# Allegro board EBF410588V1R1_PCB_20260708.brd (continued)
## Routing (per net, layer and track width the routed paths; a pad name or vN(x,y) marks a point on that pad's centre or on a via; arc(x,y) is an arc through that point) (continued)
MIPI_DPHY_CSI1_RX_D0N: length 73.6
  TOP w0.084: v1(13.26,46.28) 13.13,46.16 arc(13,46.07) 12.85,46.04 11.98,46.04 arc(11.67,45.98) 11.41,45.81 11.41,45.8 arc(11.29,45.52) 11.41,45.23 11.51,45.13 arc(11.57,44.98) 11.51,44.83 11.46,44.79 arc(11.35,44.74) 11.23,44.79 11.16,44.86 arc(10.81,45) 10.46,44.86 10.32,44.71 arc(10.22,44.48) 10.32,44.24 10.37,44.19 arc(10.37,43.89) 10.08,43.89 arc(9.79,44.01) 9.5,43.89 9.41,43.8 arc(9.2,43.49) 9.12,43.11 9.12,42.75 arc(9.09,42.59) 9,42.45 8.75,42.2 arc(8.48,41.8) 8.39,41.32 8.39,40.33 arc(8.36,40.18) 8.27,40.04 8.07,39.84 arc(7.85,39.52) 7.78,39.15 7.78,37.03 arc(7.74,36.94) 7.64,36.9 7.6,36.9 arc(7.51,36.92) 7.44,36.97 7.42,36.98 arc(7.35,37.03) 7.26,37.05 J15.12 ; v1(62.92,51.79) 62.92,51.63 arc(62.9,51.5) 62.83,51.4 62.61,51.18 arc(62.5,51.01) 62.46,50.81 62.46,50.79 arc(62.5,50.59) 62.61,50.42 62.8,50.23 arc(62.82,50.2) 62.82,50.17 62.82,49.65 arc(62.81,49.59) 62.78,49.54 62.77,49.53 arc(62.73,49.48) 62.72,49.42 CN2.54
  BOTTOM w0.084: v1(62.92,51.79) 62.92,51.61 arc(62.89,51.45) 62.81,51.33 62.54,51.06 arc(62.46,50.94) 62.43,50.79 62.43,50.62 62.23,50.42 arc(62.03,50.28) 61.79,50.24 52.05,50.24 arc(51.41,50.11) 50.86,49.74 45.51,44.4 arc(45.03,44.08) 44.47,43.96 42.76,43.96 arc(42.2,44.08) 41.72,44.4 41.65,44.46 arc(41.11,44.83) 40.47,44.95 36.04,44.95 arc(35.4,44.83) 34.85,44.46 34.1,43.71 arc(33.62,43.39) 33.06,43.28 21.93,43.28 arc(21.36,43.39) 20.88,43.71 18.75,45.84 arc(18.53,45.99) 18.27,46.04 13.67,46.04 arc(13.52,46.07) 13.39,46.16 v1(13.26,46.28)
MIPI_DPHY_CSI1_RX_D0P: length 73.7
  TOP w0.084: v1(13.26,45.4) 13.3,45.44 arc(13.33,45.48) 13.34,45.52 13.34,45.58 arc(13.32,45.66) 13.27,45.73 13.24,45.76 arc(13.15,45.82) 13.05,45.84 11.98,45.84 arc(11.75,45.8) 11.55,45.67 11.55,45.66 arc(11.49,45.52) 11.55,45.37 11.65,45.27 arc(11.77,44.98) 11.65,44.69 11.6,44.65 arc(11.35,44.54) 11.09,44.65 11.02,44.72 arc(10.81,44.8) 10.6,44.72 10.46,44.57 arc(10.42,44.48) 10.46,44.38 10.51,44.33 arc(10.51,43.75) 9.94,43.75 arc(9.79,43.82) 9.64,43.75 9.55,43.66 arc(9.38,43.41) 9.32,43.11 9.32,42.75 arc(9.27,42.51) 9.14,42.31 8.89,42.06 arc(8.66,41.72) 8.59,41.32 8.59,40.33 arc(8.54,40.1) 8.41,39.9 8.21,39.7 arc(8.04,39.45) 7.98,39.15 7.98,37.03 arc(7.88,36.8) 7.64,36.7 7.6,36.7 arc(7.51,36.68) 7.43,36.63 7.42,36.62 arc(7.35,36.57) 7.26,36.55 J15.11 ; v1(62.92,50.79) 62.84,50.7 arc(62.8,50.61) 62.84,50.52 62.94,50.42 arc(63,50.33) 63.02,50.22 63.02,49.65 arc(63.03,49.59) 63.07,49.54 63.08,49.53 arc(63.11,49.48) 63.12,49.42 CN2.56
  BOTTOM w0.084: v1(62.92,50.79) 62.76,50.79 62.63,50.65 62.63,50.54 62.37,50.28 arc(62.1,50.1) 61.79,50.04 52.05,50.04 arc(51.48,49.93) 51,49.6 45.65,44.26 arc(45.11,43.89) 44.47,43.77 42.76,43.77 arc(42.12,43.89) 41.58,44.26 41.51,44.32 arc(41.03,44.64) 40.47,44.75 36.04,44.75 arc(35.47,44.64) 34.99,44.32 34.24,43.57 arc(33.7,43.21) 33.06,43.08 21.93,43.08 arc(21.29,43.21) 20.74,43.57 18.61,45.7 arc(18.45,45.81) 18.27,45.84 18.12,45.84 arc(18.07,45.82) 18.05,45.77 arc(18.03,45.72) 17.98,45.69 17.79,45.69 arc(17.74,45.72) 17.72,45.77 arc(17.69,45.82) 17.64,45.84 17.45,45.84 arc(17.4,45.82) 17.38,45.77 arc(17.36,45.72) 17.31,45.69 17.12,45.69 arc(17.07,45.72) 17.04,45.77 arc(17.02,45.82) 16.97,45.84 16.78,45.84 arc(16.73,45.82) 16.71,45.77 arc(16.69,45.72) 16.64,45.69 16.45,45.69 arc(16.4,45.72) 16.37,45.77 arc(16.35,45.82) 16.3,45.84 16.11,45.84 arc(16.06,45.82) 16.04,45.77 arc(16.02,45.72) 15.96,45.69 15.78,45.69 arc(15.73,45.72) 15.7,45.77 arc(15.68,45.82) 15.63,45.84 15.44,45.84 arc(15.39,45.82) 15.37,45.77 arc(15.35,45.72) 15.29,45.69 15.11,45.69 arc(15.05,45.72) 15.03,45.77 arc(15.01,45.82) 14.96,45.84 14.77,45.84 arc(14.72,45.82) 14.7,45.77 arc(14.68,45.72) 14.62,45.69 14.44,45.69 arc(14.38,45.72) 14.36,45.77 arc(14.34,45.82) 14.29,45.84 14.1,45.84 arc(14.05,45.82) 14.03,45.77 arc(14.01,45.72) 13.95,45.69 13.77,45.69 arc(13.71,45.72) 13.69,45.77 arc(13.67,45.82) 13.62,45.84 13.36,45.84 arc(13.29,45.81) 13.26,45.75 v1(13.26,45.4)
MIPI_DPHY_CSI1_RX_D1N: length 73.7
  TOP w0.084: v1(63.92,51.79) 63.92,51.6 arc(63.89,51.44) 63.8,51.3 63.6,51.1 arc(63.49,50.94) 63.45,50.74 63.45,50.64 arc(63.47,50.53) 63.53,50.44 63.54,50.43 arc(63.6,50.34) 63.62,50.23 63.62,49.65 arc(63.61,49.59) 63.58,49.54 63.57,49.53 arc(63.53,49.48) 63.52,49.42 CN2.58 ; J15.8 7.26,35.05 arc(7.35,35.03) 7.42,34.98 7.43,34.97 arc(7.51,34.92) 7.6,34.9 7.75,34.9 arc(7.96,34.94) 8.13,35.06 8.74,35.66 arc(9.06,36.14) 9.17,36.71 9.17,38.42 arc(9.21,38.62) 9.32,38.78 9.65,39.11 arc(9.91,39.51) 10.01,39.98 10.01,41.27 arc(10.07,41.6) 10.26,41.89 11.37,42.99 arc(12,43.25) 12.64,42.99 arc(12.83,42.86) 13.05,42.82 13.47,42.82 arc(13.74,42.87) 13.97,43.02 13.98,43.04 arc(14.11,43.24) 14.16,43.47 14.16,43.9 arc(14.19,44.04) 14.27,44.16 14.46,44.36 arc(14.58,44.44) 14.72,44.47 14.95,44.47 arc(15.07,44.49) 15.17,44.55 15.23,44.62 arc(15.26,44.66) 15.27,44.7 v1(15.27,44.76)
  BOTTOM w0.084: v1(15.27,44.76) 15.39,44.63 arc(15.52,44.55) 15.68,44.52 17.81,44.52 arc(17.93,44.49) 18.04,44.42 19.79,42.66 arc(20.04,42.5) 20.33,42.44 33.58,42.44 arc(34.15,42.56) 34.63,42.88 35.25,43.5 arc(35.8,43.87) 36.44,43.99 40.07,43.99 arc(40.71,43.87) 41.25,43.5 41.32,43.44 arc(41.8,43.12) 42.36,43 45.01,43 arc(45.57,43.12) 46.05,43.44 51.5,48.89 arc(52.05,49.25) 52.69,49.38 62.3,49.38 arc(62.38,49.39) 62.44,49.44 63.42,50.42 63.42,50.69 arc(63.47,50.93) 63.6,51.13 63.81,51.34 arc(63.89,51.46) 63.92,51.61 v1(63.92,51.79)
MIPI_DPHY_CSI1_RX_D1P: length 73.8
  TOP w0.084: v1(63.92,50.79) 63.87,50.73 arc(63.83,50.68) 63.82,50.62 63.82,49.65 arc(63.83,49.59) 63.87,49.54 63.88,49.53 arc(63.91,49.48) 63.92,49.42 CN2.60 ; v1(15.27,43.87) 15.27,44.01 arc(15.24,44.11) 15.19,44.2 arc(15.11,44.25) 15.02,44.27 14.72,44.27 arc(14.66,44.26) 14.6,44.22 14.41,44.02 arc(14.37,43.97) 14.36,43.9 14.36,43.47 arc(14.3,43.16) 14.12,42.9 14.11,42.88 arc(13.81,42.69) 13.47,42.62 13.05,42.62 arc(12.75,42.68) 12.5,42.85 arc(12,43.05) 11.51,42.85 10.4,41.75 arc(10.26,41.53) 10.21,41.27 10.21,39.98 arc(10.1,39.43) 9.79,38.97 9.46,38.64 arc(9.39,38.54) 9.37,38.42 9.37,36.71 arc(9.24,36.06) 8.88,35.52 8.27,34.92 arc(8.03,34.76) 7.75,34.7 7.6,34.7 arc(7.51,34.68) 7.44,34.63 7.42,34.62 arc(7.35,34.57) 7.26,34.55 J15.7
  BOTTOM w0.084: v1(63.92,50.79) 63.75,50.79 63.62,50.65 63.62,50.33 63.47,50.18 arc(63.45,50.13) 63.47,50.08 arc(63.49,50.03) 63.47,49.98 63.33,49.84 arc(63.28,49.82) 63.23,49.84 63.23,49.85 arc(63.18,49.87) 63.13,49.85 62.99,49.71 arc(62.97,49.66) 62.99,49.61 arc(63.01,49.56) 62.99,49.51 62.86,49.37 arc(62.81,49.35) 62.76,49.37 arc(62.71,49.39) 62.66,49.37 62.58,49.3 arc(62.45,49.21) 62.3,49.18 52.69,49.18 arc(52.12,49.07) 51.64,48.75 46.19,43.3 arc(45.65,42.93) 45.01,42.81 42.36,42.81 arc(41.72,42.93) 41.18,43.3 41.11,43.36 arc(40.63,43.68) 40.07,43.79 36.44,43.79 arc(35.87,43.68) 35.39,43.36 34.77,42.74 arc(34.22,42.37) 33.58,42.25 20.3,42.25 arc(19.96,42.31) 19.68,42.5 19.31,42.87 arc(19.25,42.89) 19.2,42.87 arc(19.14,42.84) 19.08,42.87 18.96,42.99 arc(18.94,43.05) 18.96,43.11 arc(18.98,43.16) 18.96,43.22 18.84,43.34 arc(18.78,43.37) 18.72,43.34 arc(18.66,43.32) 18.61,43.34 18.48,43.47 arc(18.46,43.52) 18.48,43.58 arc(18.51,43.64) 18.48,43.69 18.36,43.82 arc(18.3,43.84) 18.25,43.82 18.25,43.82 arc(18.19,43.79) 18.13,43.82 18.01,43.94 arc(17.99,44) 18.01,44.05 arc(18.03,44.11) 18.01,44.17 17.9,44.28 arc(17.86,44.31) 17.81,44.32 17.45,44.32 arc(17.39,44.3) 17.37,44.24 arc(17.35,44.19) 17.3,44.17 17.11,44.17 arc(17.06,44.19) 17.04,44.24 arc(17.02,44.3) 16.96,44.32 16.78,44.32 arc(16.72,44.3) 16.7,44.24 arc(16.68,44.19) 16.63,44.17 16.44,44.17 arc(16.39,44.19) 16.37,44.24 arc(16.35,44.3) 16.29,44.32 16.11,44.32 arc(16.05,44.3) 16.03,44.24 arc(16.01,44.19) 15.96,44.17 15.77,44.17 arc(15.72,44.19) 15.7,44.24 arc(15.67,44.3) 15.62,44.32 15.42,44.32 arc(15.34,44.3) 15.28,44.26 15.27,44.25 arc(15.19,44.06) v1(15.27,43.87)
MIPI_DPHY_CSI2_RX_CLKN: length 93.6
  TOP w0.084: CN2.76 67.12,49.42 arc(67.13,49.48) 67.17,49.53 67.18,49.54 arc(67.21,49.59) 67.22,49.65 67.22,49.93 arc(67.25,50.05) 67.31,50.14 67.35,50.18 arc(67.43,50.3) 67.46,50.45 67.46,50.81 arc(67.49,50.96) 67.58,51.1 67.81,51.32 arc(67.89,51.45) 67.92,51.6 v1(67.92,51.79)
  ART03 w0.076: v1(3.74,18.78) 3.63,18.88 arc(3.53,18.95) 3.41,18.98 3.19,18.98 arc(2.82,19.13) 2.67,19.5 2.67,21.73 arc(2.69,21.86) 2.77,21.97 2.83,22.03 arc(2.86,22.08) 2.87,22.13 2.87,24.42 arc(2.99,25) 3.32,25.5 5.22,27.4 6.52,28.7 arc(6.81,29.13) 6.91,29.64 6.91,30.4 arc(7.12,31.49) 7.74,32.41 8.08,32.75 arc(8.28,33.06) 8.36,33.43 8.36,34.08 arc(8.5,34.82) 8.93,35.45 8.93,35.46 arc(9.55,35.87) 10.28,36.02 11.66,36.02 arc(11.82,36.05) 11.96,36.14 12.04,36.22 v1(12.04,36.24)
  BOTTOM w0.084: v1(3.74,18.78) 3.86,18.9 arc(3.98,18.98) 4.12,19 4.46,19 arc(4.78,19.07) 5.05,19.25 5.23,19.42 arc(5.31,19.48) 5.41,19.5 5.51,19.5 arc(5.61,19.48) 5.68,19.43 5.69,19.42 arc(5.77,19.37) 5.86,19.35 J16.10 ; v1(67.92,51.79) 67.92,51.62 arc(67.89,51.48) 67.81,51.36 67.59,51.13 arc(67.45,50.92) 67.4,50.67 67.4,48.76 arc(67.39,48.71) 67.36,48.67 64.64,45.95 arc(64.16,45.62) 63.59,45.51 54.84,45.51 arc(54.2,45.38) 53.66,45.02 47.63,38.99 arc(47.15,38.67) 46.58,38.56 41.35,38.56 arc(40.93,38.64) 40.57,38.88 40.51,38.94 arc(40.1,39.22) 39.61,39.31 21.29,39.31 arc(20.65,39.19) 20.1,38.82 17.66,36.38 arc(17.18,36.06) 16.62,35.95 12.53,35.95 arc(12.35,35.99) 12.19,36.09 v1(12.04,36.24)
MIPI_DPHY_CSI2_RX_CLKP: length 93.7
  TOP w0.084: v1(67.92,50.79) 67.83,50.79 arc(67.71,50.74) 67.67,50.62 67.67,50.38 arc(67.64,50.23) 67.55,50.1 67.45,50 arc(67.43,49.97) 67.42,49.93 67.42,49.65 arc(67.43,49.59) 67.47,49.54 67.48,49.53 arc(67.51,49.48) 67.52,49.42 CN2.78
  ART03 w0.076: v1(3.74,19.58) 3.74,19.48 arc(3.72,19.39) 3.68,19.32 3.63,19.28 arc(3.52,19.2) 3.39,19.18 3.19,19.18 arc(2.96,19.27) 2.87,19.5 2.87,21.73 arc(2.88,21.78) 2.91,21.82 2.98,21.89 arc(3.05,22) 3.07,22.13 3.07,24.42 arc(3.17,24.93) 3.46,25.36 5.36,27.25 6.67,28.56 arc(7,29.05) 7.11,29.64 7.11,30.4 arc(7.31,31.41) 7.88,32.27 8.22,32.6 arc(8.47,32.98) 8.56,33.43 8.56,34.08 arc(8.69,34.74) 9.07,35.31 9.07,35.31 arc(9.63,35.68) 10.28,35.81 11.79,35.81 arc(11.9,35.79) 12,35.73 12.04,35.69 arc(12.11,35.52) v1(12.04,35.36)
  BOTTOM w0.084: J16.9 5.86,19.85 arc(5.77,19.83) 5.69,19.78 5.68,19.77 arc(5.61,19.72) 5.51,19.7 5.41,19.7 arc(5.24,19.66) 5.09,19.56 4.91,19.39 arc(4.7,19.25) 4.46,19.2 4.03,19.2 arc(3.92,19.22) 3.83,19.28 3.81,19.31 arc(3.76,19.38) 3.74,19.47 v1(3.74,19.58) ; v1(12.04,35.36) 12.02,35.38 arc(11.96,35.51) 12.02,35.64 arc(12.14,35.72) 12.29,35.75 12.62,35.75 arc(12.67,35.73) 12.69,35.68 arc(12.71,35.63) 12.76,35.61 12.95,35.61 arc(13,35.63) 13.02,35.68 arc(13.04,35.73) 13.09,35.75 13.29,35.75 arc(13.34,35.73) 13.36,35.68 arc(13.38,35.63) 13.43,35.61 13.62,35.61 arc(13.67,35.63) 13.69,35.68 arc(13.71,35.73) 13.76,35.75 16.62,35.75 arc(17.26,35.88) 17.8,36.24 20.24,38.68 arc(20.72,39) 21.29,39.12 39.61,39.12 arc(40.02,39.03) 40.37,38.8 40.43,38.74 arc(40.85,38.46) 41.35,38.36 46.58,38.36 arc(47.22,38.49) 47.77,38.85 53.8,44.88 arc(54.28,45.2) 54.84,45.31 63.59,45.31 arc(64.24,45.44) 64.78,45.8 66.14,47.16 arc(66.2,47.19) 66.26,47.16 arc(66.33,47.13) 66.39,47.16 66.5,47.27 arc(66.53,47.33) 66.5,47.4 arc(66.47,47.46) 66.5,47.52 66.61,47.64 arc(66.67,47.66) 66.74,47.64 arc(66.8,47.61) 66.86,47.64 66.97,47.75 arc(67,47.81) 66.97,47.87 arc(66.95,47.94) 66.97,48 67.08,48.11 arc(67.15,48.14) 67.21,48.11 arc(67.27,48.08) 67.34,48.11 67.45,48.22 arc(67.47,48.28) 67.45,48.35 arc(67.42,48.41) 67.45,48.47 67.6,48.62 67.6,49.21 arc(67.62,49.27) 67.68,49.29 arc(67.74,49.32) 67.77,49.38 67.77,49.54 arc(67.74,49.6) 67.68,49.63 arc(67.62,49.65) 67.6,49.71 67.6,49.88 arc(67.62,49.94) 67.68,49.96 arc(67.74,49.99) 67.77,50.05 67.77,50.21 arc(67.74,50.27) 67.68,50.3 arc(67.62,50.32) 67.6,50.38 67.6,50.63 67.75,50.79 v1(67.92,50.79)
MIPI_DPHY_CSI2_RX_D0N: length 95.8
  TOP w0.084: v1(65.92,51.79) 65.92,51.61 arc(65.89,51.46) 65.81,51.33 65.59,51.12 arc(65.49,50.96) 65.46,50.78 65.46,50.68 arc(65.48,50.58) 65.53,50.49 65.55,50.48 arc(65.6,50.4) 65.62,50.29 65.62,49.65 arc(65.61,49.59) 65.58,49.54 65.57,49.53 arc(65.53,49.48) 65.52,49.42 CN2.68
  ART03 w0.076: v1(10.11,37.61) 10,37.5 arc(9.88,37.42) 9.75,37.4 9.49,37.4 arc(9.12,37.32) 8.81,37.12 8.49,36.79 arc(7.94,35.97) 7.75,35 7.75,34.52 arc(7.69,34.24) 7.53,34 6.61,33.08 arc(6.24,32.52) 6.1,31.86 arc(6.1,31.84) 6.1,31.83 6.1,29.66 arc(6.07,29.53) 6,29.43 1.84,25.27 arc(1.51,24.78) 1.4,24.19 1.4,19.56 arc(1.44,19.32) 1.58,19.12 1.6,19.1 arc(1.67,18.94) 1.6,18.78 1.5,18.67 arc(1.42,18.56) 1.4,18.43 1.4,17.78 arc(1.52,17.48) 1.83,17.35 1.91,17.35 arc(2.02,17.33) 2.11,17.27 v1(2.29,17.09)
  BOTTOM w0.084: v1(65.92,51.79) 65.96,51.74 arc(66.02,51.61) 65.96,51.48 65.62,51.14 arc(65.5,50.96) 65.46,50.75 65.46,50.31 65.58,50.19 65.58,49.66 arc(65.57,49.61) 65.54,49.57 64,48.02 arc(63.81,47.89) 63.58,47.85 54.41,47.85 arc(53.77,47.72) 53.22,47.36 47.37,41.5 arc(46.89,41.18) 46.32,41.07 41.12,41.07 arc(40.95,41.03) 40.81,40.94 40.75,40.88 arc(40.68,40.83) 40.59,40.81 19.76,40.81 arc(19.12,40.69) 18.58,40.32 16.75,38.49 arc(16.23,38.14) 15.62,38.02 11.65,38.02 arc(11.49,37.99) 11.36,37.91 10.94,37.48 arc(10.78,37.38) 10.6,37.34 10.56,37.34 arc(10.39,37.38) 10.25,37.47 v1(10.11,37.61) ; v1(2.29,17.09) 2.41,17.21 arc(2.53,17.29) 2.68,17.32 3.63,17.32 arc(4.01,17.4) 4.33,17.61 5.09,18.38 arc(5.23,18.47) 5.39,18.5 5.51,18.5 arc(5.61,18.48) 5.68,18.43 5.69,18.42 arc(5.77,18.37) 5.86,18.35 J16.12
MIPI_DPHY_CSI2_RX_D0P: length 95.9
  TOP w0.084: v1(65.92,50.79) 65.87,50.73 arc(65.83,50.68) 65.82,50.62 65.82,49.65 arc(65.83,49.59) 65.87,49.54 65.88,49.53 arc(65.91,49.48) 65.92,49.42 CN2.70
  ART03 w0.076: v1(10.11,36.72) 10.11,36.92 arc(10.03,37.11) 9.84,37.19 9.49,37.19 arc(9.2,37.13) 8.96,36.97 8.63,36.65 arc(8.13,35.89) 7.95,35 7.95,34.52 arc(7.88,34.16) 7.67,33.85 6.76,32.94 arc(6.42,32.44) 6.3,31.86 6.3,29.66 arc(6.26,29.46) 6.14,29.28 1.99,25.13 arc(1.7,24.7) 1.6,24.19 1.6,19.56 arc(1.63,19.4) 1.72,19.27 1.74,19.24 arc(1.87,18.94) 1.74,18.63 1.64,18.53 arc(1.61,18.48) 1.6,18.43 1.6,17.78 arc(1.67,17.62) 1.83,17.55 2.07,17.55 arc(2.22,17.61) 2.29,17.77 v1(2.29,17.98)
  BOTTOM w0.084: v1(65.92,50.79) 65.8,50.79 65.66,50.65 65.66,50.4 65.78,50.27 65.78,49.52 65.63,49.38 arc(65.6,49.31) 65.63,49.25 arc(65.66,49.18) 65.63,49.12 65.52,49.01 arc(65.46,48.98) 65.39,49.01 arc(65.33,49.04) 65.27,49.01 65.16,48.9 arc(65.13,48.84) 65.16,48.77 arc(65.18,48.71) 65.16,48.65 65.05,48.54 arc(64.98,48.51) 64.92,48.54 arc(64.86,48.56) 64.79,48.54 64.68,48.43 arc(64.66,48.36) 64.68,48.3 arc(64.71,48.24) 64.68,48.17 64.57,48.06 arc(64.51,48.04) 64.45,48.06 arc(64.38,48.09) 64.32,48.06 64.14,47.88 arc(63.88,47.71) 63.58,47.65 54.41,47.65 arc(53.84,47.54) 53.36,47.22 47.51,41.36 arc(46.96,41) 46.32,40.87 41.12,40.87 arc(41.03,40.85) 40.95,40.8 40.89,40.74 arc(40.75,40.65) 40.59,40.61 19.76,40.61 arc(19.2,40.5) 18.72,40.18 16.85,38.32 arc(16.31,37.95) 15.67,37.83 14.95,37.83 arc(14.89,37.8) 14.87,37.75 arc(14.85,37.69) 14.79,37.67 14.61,37.67 arc(14.56,37.69) 14.53,37.75 arc(14.51,37.8) 14.46,37.83 14.28,37.83 arc(14.22,37.8) 14.2,37.75 arc(14.18,37.69) 14.12,37.67 13.94,37.67 arc(13.89,37.69) 13.86,37.75 arc(13.84,37.8) 13.79,37.83 13.61,37.83 arc(13.55,37.8) 13.53,37.75 arc(13.51,37.69) 13.45,37.67 13.27,37.67 arc(13.22,37.69) 13.19,37.75 arc(13.17,37.8) 13.12,37.83 12.94,37.83 arc(12.88,37.8) 12.86,37.75 arc(12.84,37.69) 12.78,37.67 12.6,37.67 arc(12.55,37.69) 12.52,37.75 arc(12.5,37.8) 12.44,37.83 12.27,37.83 arc(12.21,37.8) 12.19,37.75 arc(12.16,37.69) 12.11,37.67 11.93,37.67 arc(11.88,37.69) 11.85,37.75 arc(11.83,37.8) 11.77,37.83 11.65,37.83 arc(11.57,37.81) 11.5,37.77 11.08,37.34 arc(10.86,37.2) 10.6,37.14 10.22,37.14 arc(10.14,37.11) 10.11,37.03 v1(10.11,36.72) ; J16.11 5.86,18.85 arc(5.77,18.83) 5.69,18.78 5.68,18.77 arc(5.61,18.72) 5.51,18.7 5.39,18.7 arc(5.15,18.65) 4.95,18.52 4.19,17.75 arc(3.93,17.58) 3.63,17.52 2.55,17.52 arc(2.45,17.54) 2.37,17.59 2.36,17.61 arc(2.3,17.69) 2.29,17.78 v1(2.29,17.98)
MIPI_DPHY_CSI2_RX_D1N: length 96.1
  TOP w0.084: v1(66.92,51.79) 66.92,51.61 arc(66.89,51.47) 66.81,51.34 66.59,51.12 arc(66.47,50.94) 66.42,50.72 66.42,49.65 arc(66.41,49.59) 66.38,49.54 66.37,49.53 arc(66.33,49.48) 66.32,49.42 CN2.72
  ART03 w0.076: v1(10.11,35.1) 9.98,34.97 arc(9.86,34.88) 9.7,34.85 9.49,34.85 arc(9.31,34.82) 9.15,34.71 arc(9.08,34.6) 9.05,34.46 9.05,33.42 arc(8.88,32.56) 8.4,31.84 7.96,31.41 arc(7.8,31.17) 7.75,30.89 7.75,28.36 arc(7.69,28.22) 7.56,28.17 7.28,28.17 arc(7,28.05) 6.88,27.77 6.88,27.76 arc(7,27.49) 7.27,27.38 7.56,27.38 arc(7.69,27.32) 7.75,27.19 7.75,26.98 arc(7.69,26.85) 7.56,26.79 6.26,26.79 arc(5.87,26.4) 6.26,26.01 7.45,26.01 arc(7.66,25.92) 7.75,25.71 7.75,25.61 arc(7.69,25.46) 7.54,25.4 4.5,25.4 arc(4.1,25.24) 3.94,24.84 3.94,22.03 arc(3.92,21.96) 3.89,21.9 3.82,21.84 arc(3.74,21.71) 3.71,21.56 3.71,20.83 arc(3.83,20.54) 4.12,20.42 arc(4.27,20.39) 4.4,20.31 v1(4.52,20.18)
  BOTTOM w0.084: J16.8 5.86,20.35 arc(5.77,20.37) 5.69,20.42 5.68,20.43 arc(5.61,20.48) 5.51,20.5 5.06,20.5 arc(4.86,20.46) 4.69,20.35 v1(4.52,20.18) ; v1(66.92,51.79) 66.92,51.61 arc(66.89,51.45) 66.81,51.33 66.59,51.11 arc(66.46,50.91) 66.41,50.66 66.41,49.04 arc(66.4,48.99) 66.37,48.94 64.35,46.93 arc(63.87,46.61) 63.3,46.49 54.45,46.49 arc(53.81,46.37) 53.27,46 47.21,39.95 arc(46.73,39.63) 46.17,39.52 41.57,39.52 arc(41.26,39.58) 40.99,39.76 40.92,39.82 arc(40.6,40.04) 40.21,40.12 20.52,40.12 arc(19.88,39.99) 19.33,39.63 17.19,37.49 arc(16.71,37.17) 16.15,37.05 11.92,37.05 arc(11.7,37.01) 11.51,36.89 11.5,36.87 arc(11.37,36.69) 11.33,36.47 11.33,35.37 arc(11.18,35.02) 10.84,34.88 10.47,34.88 arc(10.34,34.9) 10.22,34.98 v1(10.11,35.1)
MIPI_DPHY_CSI2_RX_D1P: length 96
  TOP w0.084: CN2.74 66.72,49.42 arc(66.71,49.48) 66.68,49.53 66.67,49.54 arc(66.63,49.59) 66.62,49.65 66.62,50.7 arc(66.65,50.76) 66.71,50.79 v1(66.92,50.79)
  ART03 w0.076: v1(10.11,34.21) 10.11,34.38 arc(10.03,34.57) 9.84,34.65 9.49,34.65 arc(9.39,34.63) 9.3,34.57 9.3,34.57 arc(9.26,34.52) 9.25,34.46 9.25,33.42 arc(9.07,32.49) 8.54,31.7 8.54,31.7 8.11,31.26 arc(7.99,31.09) 7.95,30.89 7.95,28.36 arc(7.83,28.08) 7.56,27.96 7.28,27.96 arc(7.14,27.91) 7.09,27.77 7.09,27.76 arc(7.14,27.63) 7.27,27.58 7.56,27.58 arc(7.83,27.47) 7.95,27.19 7.95,26.98 arc(7.83,26.71) 7.56,26.59 6.26,26.59 arc(6.07,26.4) 6.26,26.21 7.45,26.21 arc(7.8,26.06) 7.95,25.71 7.95,25.61 arc(7.83,25.32) 7.54,25.2 4.5,25.2 arc(4.24,25.09) 4.14,24.84 4.14,22.03 arc(4.11,21.88) 4.03,21.76 3.97,21.7 arc(3.93,21.63) 3.91,21.56 3.91,20.83 arc(3.97,20.69) 4.12,20.63 4.28,20.63 arc(4.5,20.72) 4.6,20.95 arc(4.59,20.99) 4.56,21.03 v1(4.52,21.07)
  BOTTOM w0.084: J16.7 5.86,20.85 arc(5.77,20.83) 5.69,20.78 5.68,20.77 arc(5.61,20.72) 5.51,20.7 5.06,20.7 arc(4.9,20.73) 4.77,20.82 v1(4.52,21.07) ; v1(66.92,50.79) 66.74,50.79 66.61,50.65 66.61,50.38 arc(66.63,50.31) 66.7,50.28 arc(66.77,50.25) 66.8,50.18 66.8,50.04 arc(66.77,49.98) 66.7,49.95 arc(66.63,49.92) 66.61,49.85 66.61,49.71 arc(66.63,49.64) 66.7,49.61 arc(66.77,49.58) 66.8,49.51 66.8,49.37 arc(66.77,49.3) 66.7,49.28 arc(66.63,49.25) 66.61,49.18 66.61,48.9 66.45,48.75 arc(66.43,48.69) 66.45,48.63 arc(66.48,48.58) 66.45,48.52 66.33,48.4 arc(66.27,48.37) 66.22,48.4 arc(66.16,48.42) 66.1,48.4 65.98,48.27 arc(65.95,48.22) 65.98,48.16 arc(66,48.1) 65.98,48.05 65.85,47.92 arc(65.8,47.9) 65.74,47.92 arc(65.68,47.95) 65.63,47.92 64.49,46.79 arc(63.95,46.42) 63.31,46.3 54.45,46.3 arc(53.89,46.18) 53.41,45.86 47.35,39.81 arc(46.81,39.45) 46.17,39.32 41.57,39.32 arc(41.18,39.4) 40.85,39.62 40.78,39.68 arc(40.52,39.86) 40.21,39.92 20.52,39.92 arc(19.95,39.81) 19.47,39.49 17.33,37.35 arc(16.79,36.98) 16.15,36.86 15.29,36.86 arc(15.23,36.83) 15.21,36.78 arc(15.19,36.73) 15.13,36.7 14.95,36.7 arc(14.9,36.73) 14.87,36.78 arc(14.85,36.83) 14.8,36.86 12.78,36.86 arc(12.72,36.83) 12.7,36.77 arc(12.67,36.7) 12.61,36.68 12.45,36.68 arc(12.39,36.7) 12.36,36.77 arc(12.33,36.83) 12.27,36.86 11.92,36.86 arc(11.77,36.83) 11.65,36.75 11.64,36.73 arc(11.56,36.61) 11.53,36.47 11.53,35.37 arc(11.32,34.88) 10.84,34.68 10.42,34.68 arc(10.31,34.66) 10.21,34.59 10.2,34.58 arc(10.13,34.48) 10.11,34.37 v1(10.11,34.21)
MIPI_DPHY_CSI3_RX_CLKN: length 94
  TOP w0.084: J18.10 5.86,54.87 arc(5.77,54.85) 5.69,54.8 5.68,54.79 arc(5.61,54.74) 5.51,54.72 5.14,54.72 arc(4.87,54.77) 4.64,54.92 v1(4.42,55.14) ; CN4.65 65.12,15.15 arc(65.13,15.2) 65.17,15.25 65.18,15.26 arc(65.21,15.31) 65.22,15.37 65.22,20.32 arc(65.11,20.89) 64.79,21.37 61.95,24.21 arc(61.47,24.53) 60.9,24.64 49.76,24.64 arc(49.12,24.77) 48.58,25.13 45.16,28.55 arc(44.68,28.87) 44.11,28.99 32.26,28.99 arc(31.62,29.11) 31.08,29.48 30.26,30.29 arc(29.92,30.8) 29.8,31.4 29.8,32.37 arc(29.59,33.43) 28.98,34.34 23.22,40.11 arc(22.74,40.43) 22.17,40.54 17.8,40.54 arc(17.57,40.58) 17.38,40.71 17.31,40.78 arc(17.19,40.86) 17.04,40.89 15.57,40.89 arc(15.4,40.86) 15.26,40.76 15.21,40.72 arc(15.18,40.63) 15.21,40.54 v1(15.28,40.47)
  ART03 w0.076: v1(15.28,40.47) 15.41,40.59 arc(15.54,40.68) 15.69,40.71 16.17,40.71 arc(16.53,40.86) 16.68,41.22 16.68,41.52 arc(16.64,41.73) 16.52,41.91 16.5,41.92 arc(16.32,42.05) 16.11,42.09 15.3,42.09 arc(14.96,42.15) 14.68,42.34 14.62,42.41 arc(14.27,42.64) 13.85,42.72 13.62,42.72 arc(13.15,42.82) 12.76,43.08 10.12,45.71 arc(9.62,46.46) 9.45,47.34 9.45,49.33 arc(9.26,49.78) 8.81,49.96 6.81,49.96 arc(6.67,50.02) 6.62,50.15 6.62,50.56 arc(6.22,50.95) 5.83,50.56 5.83,50.35 arc(5.71,50.08) 5.44,49.96 5.44,49.96 arc(5.15,50.08) 5.03,50.37 5.03,52.25 arc(5.04,52.32) 5.08,52.38 5.15,52.44 arc(5.23,52.56) 5.26,52.71 5.26,54.49 arc(5.15,54.76) 4.88,54.87 4.87,54.87 arc(4.7,54.91) 4.56,55 v1(4.42,55.14)
MIPI_DPHY_CSI3_RX_CLKP: length 94
  TOP w0.084: J18.9 5.86,54.37 arc(5.77,54.39) 5.69,54.44 5.68,54.45 arc(5.61,54.5) 5.51,54.52 4.56,54.52 arc(4.51,54.51) 4.47,54.48 4.46,54.47 arc(4.43,54.43) 4.42,54.38 v1(4.42,54.25) ; v1(15.28,41.36) 15.42,41.22 arc(15.57,41.12) 15.74,41.09 17.04,41.09 arc(17.26,41.04) 17.45,40.92 17.52,40.85 arc(17.65,40.77) 17.8,40.74 22.17,40.74 arc(22.81,40.61) 23.36,40.25 29.13,34.48 arc(29.77,33.51) 30,32.37 30,31.4 arc(30.1,30.88) 30.4,30.43 31.22,29.62 arc(31.7,29.3) 32.26,29.18 44.11,29.18 arc(44.75,29.06) 45.3,28.69 48.72,25.27 arc(49.2,24.95) 49.76,24.84 60.9,24.84 arc(61.54,24.71) 62.09,24.35 64.93,21.51 arc(65.29,20.96) 65.42,20.32 65.42,15.37 arc(65.43,15.31) 65.47,15.26 65.48,15.25 arc(65.51,15.2) 65.52,15.15 CN4.67
  ART03 w0.076: v1(15.28,41.36) 15.28,41.03 arc(15.32,40.95) 15.4,40.91 16.17,40.91 arc(16.39,41) 16.48,41.22 16.48,41.52 arc(16.45,41.65) 16.37,41.77 16.36,41.78 arc(16.24,41.86) 16.11,41.88 15.3,41.88 arc(14.88,41.97) 14.54,42.2 14.47,42.26 arc(14.19,42.45) 13.85,42.52 13.62,42.52 arc(13.08,42.63) 12.61,42.94 9.98,45.57 arc(9.44,46.38) 9.25,47.34 9.25,49.33 arc(9.12,49.63) 8.81,49.76 6.81,49.76 arc(6.53,49.87) 6.41,50.15 6.41,50.56 arc(6.22,50.75) 6.03,50.56 6.03,50.35 arc(5.86,49.93) 5.44,49.76 5.44,49.76 arc(5,49.94) 4.83,50.37 4.83,52.25 arc(4.85,52.4) 4.94,52.52 5,52.59 arc(5.04,52.64) 5.05,52.71 5.05,54.49 arc(5,54.62) 4.88,54.67 4.61,54.67 arc(4.48,54.62) 4.42,54.49 v1(4.42,54.25)
MIPI_DPHY_CSI3_RX_D0N: length 94.1
  TOP w0.084: J18.12 5.86,55.87 arc(5.77,55.85) 5.69,55.8 5.68,55.79 arc(5.61,55.74) 5.51,55.72 5.48,55.72 arc(5.38,55.74) 5.3,55.79 4.52,56.57 arc(4.33,56.7) 4.1,56.75 3.18,56.75 arc(3.02,56.78) 2.89,56.87 v1(2.67,57.09) ; CN4.61 64.32,15.15 arc(64.33,15.2) 64.37,15.25 64.38,15.26 arc(64.41,15.31) 64.42,15.37 64.42,19.88 arc(64.31,20.44) 63.99,20.92 61.5,23.41 arc(61.02,23.73) 60.46,23.84 49.43,23.84 arc(48.79,23.97) 48.24,24.33 44.82,27.75 arc(44.35,28.07) 43.78,28.19 31.93,28.19 arc(31.29,28.31) 30.74,28.68 29.98,29.44 arc(29.34,30.4) 29.11,31.54 29.11,32.36 arc(28.97,33.09) 28.55,33.71 23.17,39.1 arc(22.69,39.42) 22.12,39.53 14.31,39.53 arc(14.25,39.51) 14.22,39.45 v1(14.22,39.19)
  ART03 w0.076: v1(2.67,57.09) 2.5,56.92 arc(2.41,56.87) 2.31,56.85 2.18,56.85 1.91,56.57 arc(1.72,56.1) 1.91,55.63 3.26,54.29 arc(3.63,53.74) 3.76,53.08 3.76,50.88 arc(4.21,48.62) 5.5,46.69 arc(6.49,46.03) 7.66,45.8 7.66,45.8 arc(8.56,45.62) 9.32,45.11 12.43,42 arc(12.76,41.51) 12.88,40.92 12.88,40.55 arc(12.95,40.16) 13.17,39.84 13.34,39.67 arc(13.5,39.56) 13.68,39.53 13.69,39.53 arc(13.87,39.49) 14.02,39.39 v1(14.22,39.19)
MIPI_DPHY_CSI3_RX_D0P: length 94
  TOP w0.084: v1(14.22,40.07) 14.4,39.9 arc(14.59,39.77) 14.81,39.73 22.12,39.73 arc(22.76,39.6) 23.31,39.24 28.69,33.85 arc(29.15,33.17) 29.31,32.36 29.31,31.54 arc(29.52,30.48) 30.12,29.58 30.88,28.82 arc(31.36,28.5) 31.93,28.38 43.78,28.38 arc(44.42,28.26) 44.97,27.89 48.38,24.47 arc(48.86,24.15) 49.43,24.04 60.46,24.04 arc(61.1,23.91) 61.64,23.55 64.13,21.06 arc(64.49,20.52) 64.62,19.88 64.62,15.37 arc(64.63,15.31) 64.67,15.26 64.68,15.25 arc(64.71,15.2) 64.72,15.15 CN4.63 ; v1(2.67,56.2) 2.67,56.3 arc(2.68,56.38) 2.73,56.45 2.75,56.47 arc(2.84,56.53) 2.93,56.55 4.1,56.55 arc(4.25,56.52) 4.38,56.43 5.16,55.65 arc(5.31,55.55) 5.48,55.52 5.51,55.52 arc(5.61,55.5) 5.68,55.45 5.69,55.44 arc(5.77,55.39) 5.86,55.37 J18.11
  ART03 w0.076: v1(14.22,40.07) 14.22,39.98 14.15,39.9 arc(13.96,39.78) 13.73,39.73 13.68,39.73 arc(13.57,39.75) 13.49,39.81 13.32,39.98 arc(13.14,40.24) 13.08,40.55 13.08,40.55 13.08,40.92 arc(12.95,41.58) 12.58,42.14 9.47,45.25 arc(8.64,45.81) 7.66,46 arc(6.57,46.22) 5.64,46.84 arc(4.4,48.69) 3.96,50.88 3.96,53.08 arc(3.82,53.81) 3.4,54.43 2.06,55.78 arc(1.92,56.1) 2.06,56.43 2.27,56.64 2.5,56.64 arc(2.63,56.58) 2.69,56.45 2.69,56.23 v1(2.67,56.2)
MIPI_DPHY_CSI3_RX_D1N: length 93.9
  TOP w0.084: v1(11.98,40.77) 11.98,40.93 arc(12,41.05) 12.07,41.15 12.08,41.16 arc(12.18,41.23) 12.3,41.25 12.85,41.25 arc(13.16,41.13) 13.28,40.82 13.28,39.13 arc(13.35,38.81) 13.53,38.54 13.54,38.52 arc(13.82,38.34) 14.14,38.28 15.51,38.28 arc(15.8,38.34) 16.05,38.5 16.17,38.62 arc(16.29,38.71) 16.44,38.73 21.89,38.73 arc(22.46,38.62) 22.94,38.3 27.79,33.45 arc(28.22,32.8) 28.38,32.03 28.38,31.13 arc(28.6,30) 29.24,29.05 30.34,27.95 arc(30.88,27.59) 31.53,27.46 43.38,27.46 arc(43.94,27.34) 44.42,27.02 47.91,23.53 arc(48.46,23.17) 49.1,23.04 60.04,23.04 arc(60.6,22.93) 61.08,22.61 63.19,20.5 arc(63.51,20.02) 63.62,19.46 63.62,15.37 arc(63.61,15.31) 63.58,15.26 63.57,15.25 arc(63.53,15.2) 63.52,15.15 CN4.57 ; J18.8 5.86,53.87 arc(5.77,53.85) 5.69,53.8 5.68,53.79 arc(5.61,53.74) 5.51,53.72 3.18,53.72 arc(3.02,53.75) 2.89,53.84 v1(2.67,54.06)
  ART03 w0.076: v1(11.98,40.77) 11.86,40.89 arc(11.75,40.97) 11.61,41 arc(11.39,41.04) 11.2,41.16 9.69,42.68 arc(9.08,43.09) 8.36,43.23 7.06,43.23 arc(6.37,43.37) 5.79,43.76 5.17,44.38 arc(5.05,44.66) 5.17,44.94 5.5,45.27 arc(5.56,45.41) 5.5,45.54 5.5,45.54 arc(5.37,45.6) 5.23,45.54 4.9,45.21 arc(4.62,45.09) 4.34,45.21 4.01,45.54 arc(3.84,45.79) 3.78,46.08 3.78,46.72 arc(3.66,47.34) 3.31,47.86 arc(2.1,49.67) 1.68,51.81 1.68,53.18 arc(1.73,53.43) 1.87,53.64 1.94,53.72 arc(2.09,53.81) 2.26,53.85 2.31,53.85 arc(2.44,53.87) 2.55,53.95 v1(2.67,54.06)
MIPI_DPHY_CSI3_RX_D1P: length 94
  TOP w0.084: v1(11.98,41.66) 12.09,41.55 arc(12.2,41.48) 12.33,41.45 12.85,41.45 arc(13.3,41.27) 13.48,40.82 13.48,39.13 arc(13.53,38.89) 13.67,38.68 13.69,38.66 arc(13.89,38.52) 14.14,38.48 15.51,38.48 arc(15.73,38.52) 15.91,38.64 16.03,38.76 arc(16.22,38.89) 16.44,38.93 21.89,38.93 arc(22.53,38.81) 23.08,38.44 27.93,33.59 arc(28.41,32.88) 28.57,32.03 28.57,31.13 arc(28.78,30.08) 29.38,29.19 30.48,28.09 arc(30.96,27.77) 31.53,27.66 43.38,27.66 arc(44.02,27.53) 44.56,27.16 48.05,23.67 arc(48.53,23.35) 49.1,23.24 60.04,23.24 arc(60.68,23.11) 61.22,22.75 63.33,20.64 arc(63.69,20.1) 63.82,19.46 63.82,15.37 arc(63.83,15.31) 63.87,15.26 63.88,15.25 arc(63.91,15.2) 63.92,15.15 CN4.59 ; J18.7 5.86,53.37 arc(5.77,53.39) 5.69,53.44 5.68,53.45 arc(5.61,53.5) 5.51,53.52 2.92,53.52 arc(2.88,53.51) 2.84,53.48 2.72,53.36 arc(2.68,53.31) 2.67,53.25 v1(2.67,53.17)
  ART03 w0.076: v1(2.67,53.17) 2.67,53.39 arc(2.65,53.48) 2.6,53.56 arc(2.51,53.62) 2.4,53.64 2.26,53.64 arc(2.17,53.63) 2.09,53.57 2.01,53.5 arc(1.91,53.35) 1.88,53.18 1.88,51.81 arc(2.29,49.75) 3.45,48.01 arc(3.85,47.42) 3.99,46.72 3.99,46.08 arc(4.03,45.86) 4.15,45.69 4.49,45.35 arc(4.62,45.29) 4.75,45.35 5.09,45.69 arc(5.37,45.8) 5.65,45.69 5.65,45.68 arc(5.76,45.41) 5.65,45.13 5.31,44.79 arc(5.26,44.66) 5.31,44.52 5.93,43.9 arc(6.45,43.56) 7.06,43.43 8.36,43.43 arc(9.15,43.28) 9.83,42.82 11.35,41.31 arc(11.47,41.23) 11.61,41.2 11.74,41.2 arc(11.91,41.27) 11.98,41.44 v1(11.98,41.66)
MIPI_DPHY_CSI4_RX_CLKN: length 73.6
  TOP w0.084: CN4.51 62.32,15.15 arc(62.33,15.2) 62.37,15.25 62.38,15.26 arc(62.41,15.31) 62.42,15.37 62.42,18.55 arc(62.31,19.11) 61.99,19.59 60.94,20.65 arc(60.46,20.97) 59.89,21.08 48.25,21.08 arc(47.6,21.21) 47.06,21.57 43.1,25.53 arc(42.62,25.85) 42.05,25.96 30.91,25.96 arc(30.27,26.09) 29.73,26.46 27.26,28.92 arc(26.84,29.55) 26.7,30.29 26.7,31.65 arc(26.66,31.81) 26.57,31.95 26.48,32.05 arc(26.42,32.08) 26.36,32.09 v1(26.28,32.09)
  BOTTOM w0.084: v1(26.28,32.09) 26.38,32.09 arc(26.45,32.11) 26.51,32.15 26.53,32.17 arc(26.57,32.23) 26.58,32.3 26.58,32.73 arc(26.45,33.05) 26.14,33.18 19.07,33.18 arc(18.61,33.09) 18.23,32.83 arc(17.85,32.58) 17.4,32.49 9.9,32.49 arc(9.14,32.8) 8.82,33.57 8.82,37.85 arc(8.57,38.45) 7.96,38.7 7.57,38.7 arc(7.51,38.69) 7.46,38.66 7.4,38.6 arc(7.35,38.56) 7.28,38.55 J17.10
MIPI_DPHY_CSI4_RX_CLKP: length 73.7
  TOP w0.084: v1(27.09,32.09) 26.98,31.99 arc(26.92,31.89) 26.89,31.77 26.89,30.29 arc(27.03,29.63) 27.4,29.06 29.87,26.6 arc(30.35,26.27) 30.91,26.16 42.05,26.16 arc(42.7,26.03) 43.24,25.67 47.2,21.71 arc(47.68,21.39) 48.25,21.28 59.89,21.28 arc(60.53,21.15) 61.08,20.79 62.13,19.73 arc(62.49,19.19) 62.62,18.55 62.62,15.37 arc(62.63,15.31) 62.67,15.26 62.68,15.25 arc(62.71,15.2) 62.72,15.15 CN4.53
  BOTTOM w0.084: J17.9 7.28,39.05 arc(7.35,39.04) 7.4,39 7.46,38.94 arc(7.51,38.91) 7.57,38.9 7.96,38.9 arc(8.71,38.59) 9.02,37.85 9.02,33.57 arc(9.28,32.94) 9.9,32.68 17.4,32.68 arc(17.77,32.76) 18.08,32.97 arc(18.53,33.27) 19.07,33.38 26.14,33.38 arc(26.59,33.19) 26.78,32.73 26.78,32.56 arc(26.81,32.41) 26.9,32.28 v1(27.09,32.09)
MIPI_DPHY_CSI4_RX_D0N: length 73.6
  TOP w0.084: v1(25.22,30.73) 25.31,30.73 arc(25.38,30.71) 25.44,30.67 25.51,30.6 arc(25.59,30.48) 25.62,30.33 25.62,29.92 arc(25.71,29.47) 25.97,29.09 29.4,25.66 arc(29.94,25.29) 30.58,25.16 41.72,25.16 arc(42.29,25.05) 42.77,24.73 46.73,20.77 arc(47.27,20.41) 47.91,20.28 59.55,20.28 arc(60.12,20.17) 60.6,19.85 61.19,19.25 arc(61.51,18.77) 61.62,18.2 61.62,15.37 arc(61.61,15.31) 61.58,15.26 61.57,15.25 arc(61.53,15.2) 61.52,15.15 CN4.47
  BOTTOM w0.084: v1(25.22,30.73) 25.3,30.73 arc(25.36,30.74) 25.41,30.77 25.46,30.82 arc(25.52,30.91) 25.54,31.02 25.54,31.55 arc(25.36,32) 24.91,32.19 24.47,32.19 arc(24.32,32.13) 24.26,31.98 24.26,31.62 arc(23.85,31.22) 23.44,31.62 23.44,31.98 arc(23.38,32.13) 23.23,32.19 19.63,32.19 arc(19.31,32.12) 19.04,31.94 18.83,31.73 arc(18.35,31.41) 17.78,31.3 9.09,31.3 arc(8.45,31.56) 8.18,32.21 8.18,37.25 arc(8.05,37.57) 7.74,37.7 7.57,37.7 arc(7.51,37.69) 7.46,37.66 7.4,37.6 arc(7.35,37.56) 7.28,37.55 J17.12
MIPI_DPHY_CSI4_RX_D0P: length 73.6
  TOP w0.084: v1(26.02,30.73) 25.91,30.62 arc(25.84,30.51) 25.82,30.39 25.82,29.92 arc(25.89,29.54) 26.11,29.23 29.54,25.8 arc(30.02,25.47) 30.58,25.36 41.72,25.36 arc(42.36,25.23) 42.91,24.87 46.87,20.91 arc(47.35,20.59) 47.91,20.48 59.55,20.48 arc(60.19,20.35) 60.74,19.99 61.33,19.39 arc(61.69,18.85) 61.82,18.2 61.82,15.37 arc(61.83,15.31) 61.87,15.26 61.88,15.25 arc(61.91,15.2) 61.92,15.15 CN4.49
  BOTTOM w0.084: v1(26.02,30.73) 25.86,30.89 arc(25.77,31.02) 25.74,31.17 25.74,31.55 arc(25.5,32.14) 24.91,32.38 24.47,32.38 arc(24.18,32.27) 24.06,31.98 24.06,31.62 arc(23.85,31.41) 23.64,31.62 23.64,31.98 arc(23.52,32.27) 23.23,32.38 19.63,32.38 arc(19.24,32.31) 18.9,32.08 18.69,31.87 arc(18.27,31.59) 17.78,31.5 9.09,31.5 arc(8.59,31.7) 8.38,32.21 8.38,37.25 arc(8.19,37.71) 7.74,37.9 7.57,37.9 arc(7.51,37.91) 7.46,37.94 7.4,38 arc(7.35,38.04) 7.28,38.05 J17.11
MIPI_DPHY_CSI4_RX_D1N: length 73.7
  TOP w0.084: v1(22.09,34.09) 22.09,34.36 arc(22.13,34.45) 22.23,34.49 22.46,34.49 arc(22.69,34.45) 22.89,34.32 23.49,33.71 arc(23.93,33.05) 24.08,32.27 24.08,31.18 arc(24.33,29.94) 25.03,28.89 29.07,24.86 arc(29.61,24.49) 30.25,24.36 41.39,24.36 arc(41.96,24.25) 42.44,23.93 46.4,19.97 arc(46.94,19.61) 47.58,19.48 59.11,19.48 arc(59.67,19.37) 60.15,19.05 60.58,18.62 arc(60.9,18.14) 61.01,17.57 61.01,16.23 arc(61,16.18) 60.98,16.15 60.91,16.08 arc(60.85,15.98) 60.82,15.87 60.82,15.37 arc(60.81,15.31) 60.78,15.26 60.77,15.25 arc(60.73,15.2) 60.72,15.15 CN4.43
  BOTTOM w0.084: v1(22.09,34.09) 22.09,34.2 arc(22.08,34.29) 22.03,34.36 22.02,34.37 arc(21.94,34.42) 21.86,34.44 20.97,34.44 arc(20.69,34.56) 20.57,34.85 20.57,34.92 arc(20.5,35.07) 20.36,35.13 20.3,35.13 arc(20.19,35.09) 20.15,34.98 20.15,34.85 arc(20.03,34.56) 19.74,34.44 19.09,34.44 arc(18.3,34.28) 17.63,33.83 arc(17.01,33.42) 16.28,33.27 10.4,33.27 arc(9.73,33.55) 9.45,34.22 9.45,39.14 arc(9.29,39.54) 8.89,39.7 7.57,39.7 arc(7.51,39.69) 7.46,39.66 7.4,39.6 arc(7.35,39.56) 7.28,39.55 J17.8
MIPI_DPHY_CSI4_RX_D1P: length 73.7
  TOP w0.084: CN4.45 61.12,15.15 arc(61.11,15.2) 61.08,15.25 61.07,15.26 arc(61.03,15.31) 61.02,15.37 61.02,15.87 arc(61.03,15.91) 61.05,15.94 61.12,16.01 arc(61.19,16.11) 61.21,16.23 61.21,17.57 arc(61.08,18.21) 60.72,18.76 60.29,19.19 arc(59.75,19.55) 59.11,19.68 47.58,19.68 arc(47.02,19.79) 46.54,20.11 42.58,24.07 arc(42.03,24.43) 41.39,24.56 30.25,24.56 arc(29.69,24.67) 29.21,25 25.17,29.03 arc(24.51,30.01) 24.28,31.18 24.28,32.27 arc(24.11,33.13) 23.63,33.85 23.03,34.46 arc(22.76,34.63) 22.46,34.69 22.31,34.69 arc(22.16,34.75) 22.09,34.9 v1(22.09,34.98)
  BOTTOM w0.084: J17.7 7.28,40.05 arc(7.35,40.04) 7.4,40 7.46,39.94 arc(7.51,39.91) 7.57,39.9 8.89,39.9 arc(9.43,39.68) 9.65,39.14 9.65,34.22 arc(9.87,33.69) 10.4,33.47 16.28,33.47 arc(16.93,33.6) 17.49,33.97 arc(18.22,34.46) 19.09,34.64 19.74,34.64 arc(19.89,34.7) 19.95,34.85 19.95,34.98 arc(20.05,35.23) 20.3,35.33 20.36,35.33 arc(20.64,35.21) 20.76,34.92 20.76,34.85 arc(20.83,34.7) 20.97,34.64 21.58,34.64 arc(21.74,34.67) 21.87,34.75 v1(22.09,34.98)
MIPI_DPHY_DSI_TX_CLKN: length 90.3
  TOP w0.084: v1(77.52,50.79) 77.66,50.79 arc(77.74,50.75) 77.77,50.67 77.77,50.46 arc(77.81,50.3) 77.89,50.17 77.96,50.1 arc(78.01,50.04) 78.02,49.96 78.02,49.65 arc(78.01,49.59) 77.98,49.54 77.97,49.53 arc(77.93,49.48) 77.92,49.42 CN3.12 ; v1(130.21,31.76) 130.21,31.61 arc(130.24,31.49) 130.3,31.39 130.32,31.38 arc(130.42,31.31) 130.55,31.28 131.11,31.28 arc(131.24,31.26) 131.34,31.19 131.35,31.18 arc(131.42,31.07) 131.44,30.95 131.44,30.59 arc(131.51,30.44) 131.66,30.38 132.77,30.38 arc(133.7,29.99) 134.09,29.06 134.09,27.66 arc(134.2,27.1) 134.52,26.62 134.69,26.44 arc(135.17,26.12) 135.74,26.01 136.77,26.01 arc(137.41,25.88) 137.96,25.52 139.15,24.33 arc(139.63,24.01) 140.19,23.89 142.45,23.89 arc(142.54,23.91) 142.62,23.96 142.63,23.98 arc(142.7,24.03) 142.8,24.05 J13.24
  ART03 w0.076: v1(130.21,31.76) 130.28,31.69 130.28,31.5 arc(130.22,31.37) 130.09,31.31 123.52,31.31 arc(123.01,31.41) 122.58,31.7 117.25,37.03 arc(116.97,37.46) 116.87,37.96 116.87,38.95 arc(116.79,39.35) 116.56,39.68 114.83,41.41 arc(114.34,41.74) 113.75,41.86 98.01,41.86 arc(97.5,41.96) 97.07,42.25 96.1,43.22 arc(95.6,43.55) 95.02,43.67 93.48,43.67 arc(93.37,43.69) 93.28,43.75 93.27,43.76 arc(93.21,43.85) 93.19,43.95 v1(93.19,44.14)
  BOTTOM w0.084: v1(77.52,50.79) 77.43,50.79 arc(77.32,50.74) 77.27,50.63 77.27,50.38 arc(77.29,50.32) 77.35,50.3 arc(77.4,50.28) 77.42,50.23 77.42,50.04 arc(77.4,49.99) 77.35,49.97 arc(77.29,49.95) 77.27,49.89 77.27,49.7 arc(77.29,49.65) 77.35,49.63 arc(77.4,49.61) 77.42,49.56 77.42,49.37 arc(77.4,49.32) 77.35,49.3 arc(77.29,49.27) 77.27,49.22 77.27,49.03 arc(77.29,48.98) 77.35,48.96 arc(77.4,48.94) 77.42,48.89 77.42,48.7 arc(77.4,48.65) 77.35,48.63 arc(77.29,48.6) 77.27,48.55 77.27,48.33 arc(77.32,48.07) 77.47,47.85 78.55,46.77 arc(78.92,46.23) 79.04,45.58 79.04,44.12 arc(79.48,43.07) 80.52,42.64 84.36,42.64 arc(84.51,42.7) 84.57,42.85 84.57,43.36 arc(84.98,43.76) 85.39,43.36 85.39,42.85 arc(85.45,42.7) 85.6,42.64 86.78,42.64 arc(87.35,42.75) 87.83,43.07 87.98,43.23 arc(88.52,43.59) 89.17,43.72 90.38,43.72 arc(90.43,43.74) 90.45,43.78 90.45,43.78 arc(90.47,43.83) 90.51,43.85 90.72,43.85 arc(90.76,43.83) 90.78,43.78 90.78,43.78 arc(90.8,43.74) 90.85,43.72 91.05,43.72 arc(91.1,43.74) 91.12,43.78 91.12,43.78 arc(91.14,43.83) 91.19,43.85 91.39,43.85 arc(91.44,43.83) 91.45,43.78 91.45,43.78 arc(91.47,43.74) 91.52,43.72 91.72,43.72 arc(91.77,43.74) 91.79,43.78 91.79,43.78 arc(91.81,43.83) 91.86,43.85 92.06,43.85 arc(92.11,43.83) 92.13,43.78 92.13,43.78 arc(92.14,43.74) 92.19,43.72 92.39,43.72 arc(92.44,43.74) 92.46,43.78 92.46,43.78 arc(92.48,43.83) 92.53,43.85 92.73,43.85 arc(92.78,43.83) 92.8,43.78 92.8,43.78 arc(92.81,43.74) 92.86,43.72 93.09,43.72 arc(93.2,43.76) 93.24,43.87 93.24,44.09 v1(93.19,44.14)
MIPI_DPHY_DSI_TX_CLKP: length 90.3
  TOP w0.084: v1(77.52,51.79) 77.52,51.6 arc(77.55,51.45) 77.64,51.31 77.88,51.08 arc(77.95,50.97) 77.98,50.83 77.98,50.51 arc(78,50.38) 78.08,50.27 78.1,50.24 arc(78.19,50.11) 78.22,49.96 78.22,49.65 arc(78.23,49.59) 78.27,49.54 78.28,49.53 arc(78.31,49.48) 78.32,49.42 CN3.14 ; v1(130.21,30.87) 130.33,30.98 arc(130.44,31.06) 130.58,31.09 131.11,31.09 arc(131.16,31.08) 131.2,31.05 131.21,31.04 arc(131.24,31) 131.25,30.95 131.25,30.59 arc(131.37,30.3) 131.66,30.18 132.77,30.18 arc(133.56,29.85) 133.89,29.06 133.89,27.66 arc(134.02,27.02) 134.38,26.48 134.55,26.3 arc(135.1,25.94) 135.74,25.81 136.77,25.81 arc(137.34,25.7) 137.82,25.38 139.01,24.19 arc(139.55,23.82) 140.19,23.7 142.45,23.7 arc(142.54,23.68) 142.62,23.63 142.63,23.62 arc(142.7,23.56) 142.8,23.55 J13.23
  ART03 w0.076: v1(130.21,30.87) 130.09,30.99 arc(129.96,31.08) 129.81,31.11 123.52,31.11 arc(122.93,31.22) 122.44,31.55 117.11,36.88 arc(116.78,37.38) 116.66,37.96 116.66,38.95 arc(116.6,39.27) 116.42,39.53 114.69,41.27 arc(114.26,41.56) 113.75,41.66 98.01,41.66 arc(97.42,41.77) 96.93,42.1 95.95,43.08 arc(95.52,43.36) 95.02,43.47 93.55,43.47 arc(93.42,43.44) 93.31,43.36 v1(93.19,43.25)
  BOTTOM w0.084: v1(93.19,43.25) 93.19,43.28 arc(93.12,43.45) 92.96,43.52 89.17,43.52 arc(88.6,43.41) 88.12,43.09 87.97,42.93 arc(87.43,42.57) 86.78,42.44 85.6,42.44 arc(85.31,42.56) 85.19,42.85 85.19,43.36 arc(84.98,43.57) 84.77,43.36 84.77,42.85 arc(84.65,42.56) 84.36,42.44 80.52,42.44 arc(79.34,42.93) 78.85,44.12 78.85,45.58 arc(78.73,46.15) 78.41,46.63 77.33,47.71 arc(77.14,48) 77.07,48.33 77.07,50.82 arc(77.11,50.98) 77.2,51.11 77.41,51.32 arc(77.49,51.45) 77.52,51.6 v1(77.52,51.79)
MIPI_DPHY_DSI_TX_D0N: length 91
  TOP w0.084: J13.27 142.8,25.55 arc(142.71,25.53) 142.63,25.48 142.62,25.46 arc(142.54,25.41) 142.45,25.39 140.98,25.39 arc(140.41,25.51) 139.93,25.83 138.9,26.86 arc(138.35,27.23) 137.71,27.36 137.39,27.36 arc(136.83,27.47) 136.35,27.79 135.49,28.65 arc(135.16,29.13) 135.05,29.7 135.05,30.33 arc(134.96,30.8) 134.7,31.19 134.64,31.24 arc(134.37,31.42) 134.06,31.49 133.59,31.49 arc(133.42,31.52) 133.28,31.62 133.27,31.63 arc(133.23,31.69) 133.21,31.76 v1(133.21,31.98) ; v1(79.51,50.79) 79.57,50.72 arc(79.61,50.66) 79.62,50.59 79.62,49.65 arc(79.61,49.59) 79.58,49.54 79.57,49.53 arc(79.53,49.48) 79.52,49.42 CN3.20
  ART03 w0.076: v1(93.22,46.95) 93.17,46.89 93.17,46.64 arc(93.21,46.54) 93.3,46.5 94.79,46.5 arc(95.37,46.38) 95.86,46.05 97.79,44.13 arc(98.22,43.84) 98.73,43.74 116.01,43.74 arc(116.6,43.62) 117.09,43.29 120.76,39.62 arc(121.09,39.13) 121.21,38.54 121.21,37.1 arc(121.31,36.59) 121.6,36.16 123.54,34.22 arc(123.97,33.93) 124.47,33.83 129.83,33.83 arc(130.42,33.72) 130.91,33.39 132.73,31.56 arc(132.78,31.53) 132.84,31.52 132.93,31.52 arc(133.06,31.55) 133.17,31.62 133.25,31.7 arc(133.3,31.82) 133.25,31.95 v1(133.21,31.98)
  BOTTOM w0.084: v1(93.22,46.95) 93.22,46.61 arc(93.19,46.53) 93.11,46.5 92.23,46.5 arc(92.18,46.52) 92.16,46.57 arc(92.14,46.61) 92.09,46.63 91.89,46.63 arc(91.84,46.61) 91.82,46.57 arc(91.8,46.52) 91.75,46.5 91.56,46.5 arc(91.51,46.52) 91.49,46.57 arc(91.47,46.61) 91.42,46.63 91.22,46.63 arc(91.17,46.61) 91.15,46.57 arc(91.13,46.52) 91.08,46.5 90.88,46.5 arc(90.84,46.52) 90.82,46.57 arc(90.8,46.61) 90.75,46.63 90.55,46.63 arc(90.5,46.61) 90.48,46.57 arc(90.46,46.52) 90.41,46.5 90.21,46.5 arc(90.17,46.52) 90.15,46.57 arc(90.13,46.61) 90.08,46.63 89.88,46.63 arc(89.83,46.61) 89.81,46.57 arc(89.79,46.52) 89.74,46.5 89.54,46.5 arc(89.5,46.52) 89.48,46.57 arc(89.46,46.61) 89.41,46.63 89.21,46.63 arc(89.16,46.61) 89.14,46.57 arc(89.12,46.52) 89.07,46.5 88.87,46.5 arc(88.82,46.52) 88.81,46.57 arc(88.79,46.61) 88.74,46.63 88.54,46.63 arc(88.49,46.61) 88.47,46.57 arc(88.45,46.52) 88.4,46.5 88.2,46.5 arc(88.15,46.52) 88.13,46.57 arc(88.11,46.61) 88.07,46.63 87.87,46.63 arc(87.82,46.61) 87.8,46.57 arc(87.78,46.52) 87.73,46.5 87.34,46.5 arc(87.05,46.38) 86.93,46.09 86.93,45.59 arc(86.88,45.47) 86.75,45.42 85.98,45.42 arc(85.87,45.46) 85.83,45.57 85.83,46.03 arc(85.71,46.32) 85.42,46.44 84.46,46.44 arc(84.25,46.65) 84.46,46.86 85.42,46.86 arc(85.83,47.27) 85.42,47.67 84.48,47.67 arc(84.27,47.88) 84.48,48.09 85.42,48.09 arc(85.71,48.21) 85.83,48.5 85.83,48.76 arc(85.82,48.79) 85.8,48.82 85.66,48.96 arc(85.49,49.08) 85.28,49.12 79.64,49.12 arc(79.36,49.23) 79.24,49.51 79.24,49.72 arc(79.27,49.78) 79.32,49.8 arc(79.38,49.82) 79.4,49.88 79.4,50.06 arc(79.38,50.11) 79.32,50.14 arc(79.27,50.16) 79.24,50.21 79.24,50.64 arc(79.28,50.74) 79.39,50.79 v1(79.51,50.79)
MIPI_DPHY_DSI_TX_D0P: length 90.9
  TOP w0.084: CN3.22 79.92,49.42 arc(79.91,49.48) 79.88,49.53 79.87,49.54 arc(79.83,49.59) 79.82,49.65 79.82,50.42 arc(79.83,50.46) 79.85,50.48 79.9,50.53 arc(79.94,50.6) 79.96,50.69 79.96,50.81 arc(79.92,50.99) 79.82,51.14 79.6,51.36 arc(79.53,51.48) 79.5,51.62 v1(79.5,51.79) ; J13.26 142.8,25.05 arc(142.71,25.06) 142.63,25.12 142.62,25.13 arc(142.54,25.18) 142.45,25.2 140.98,25.2 arc(140.34,25.32) 139.79,25.69 138.76,26.72 arc(138.28,27.05) 137.71,27.16 137.39,27.16 arc(136.75,27.29) 136.21,27.65 135.34,28.51 arc(134.98,29.05) 134.85,29.7 134.85,30.33 arc(134.78,30.72) 134.55,31.05 134.5,31.1 arc(134.3,31.24) 134.06,31.29 133.48,31.29 arc(133.41,31.28) 133.35,31.24 v1(133.21,31.1)
  ART03 w0.076: v1(133.21,31.1) 133.09,31.22 arc(132.98,31.29) 132.85,31.32 132.84,31.32 arc(132.7,31.34) 132.59,31.42 130.77,33.24 arc(130.34,33.53) 129.83,33.63 124.47,33.63 arc(123.89,33.75) 123.4,34.08 121.45,36.02 arc(121.12,36.51) 121.01,37.1 121.01,38.54 arc(120.9,39.05) 120.62,39.48 116.95,43.15 arc(116.52,43.43) 116.01,43.54 98.73,43.54 arc(98.14,43.65) 97.65,43.98 95.72,45.91 arc(95.29,46.2) 94.79,46.3 93.62,46.3 arc(93.47,46.27) 93.34,46.18 v1(93.22,46.06)
  BOTTOM w0.084: v1(79.5,51.79) 79.5,51.61 arc(79.47,51.47) 79.39,51.35 79.17,51.13 arc(79.08,50.99) 79.04,50.83 79.04,49.51 arc(79.22,49.09) 79.64,48.92 85.28,48.92 arc(85.41,48.89) 85.52,48.82 85.63,48.71 85.63,48.5 arc(85.57,48.35) 85.42,48.29 84.48,48.29 arc(84.07,47.88) 84.48,47.48 85.42,47.48 arc(85.63,47.27) 85.42,47.06 84.46,47.06 arc(84.05,46.65) 84.46,46.24 85.42,46.24 arc(85.57,46.18) 85.63,46.03 85.63,45.57 arc(85.73,45.32) 85.98,45.22 86.75,45.22 arc(87.02,45.33) 87.13,45.59 87.13,46.09 arc(87.19,46.24) 87.34,46.3 92.81,46.3 arc(92.96,46.27) 93.09,46.18 v1(93.22,46.06)
MIPI_DPHY_DSI_TX_D1N: length 91.1
  TOP w0.084: v1(132.23,29.38) 132.23,29.13 arc(132.28,28.99) 132.42,28.93 132.73,28.93 arc(133.05,28.8) 133.17,28.49 133.17,26.98 arc(133.29,26.41) 133.61,25.93 134.34,25.2 arc(134.82,24.88) 135.38,24.77 136.21,24.77 arc(136.85,24.64) 137.4,24.27 138.84,22.83 arc(139.32,22.51) 139.89,22.39 142.45,22.39 arc(142.54,22.41) 142.62,22.46 142.63,22.48 arc(142.71,22.53) 142.8,22.55 J13.21 ; v1(78.52,50.79) 78.7,50.79 arc(78.79,50.75) 78.82,50.67 78.82,49.65 arc(78.81,49.59) 78.78,49.54 78.77,49.53 arc(78.73,49.48) 78.72,49.42 CN3.16
  ART03 w0.076: v1(94.77,45.46) 94.77,45.28 arc(94.79,45.17) 94.85,45.08 94.86,45.07 arc(94.95,45.01) 95.05,44.99 95.33,44.99 arc(95.65,44.93) 95.92,44.75 97.43,43.24 arc(97.86,42.95) 98.36,42.85 115.89,42.85 arc(116.14,42.8) 116.35,42.66 118.4,40.61 arc(118.73,40.12) 118.85,39.53 118.85,37.3 arc(118.91,36.98) 119.09,36.72 122.63,33.18 arc(123.05,32.89) 123.56,32.79 129.54,32.79 arc(130.13,32.68) 130.62,32.34 131.07,31.9 arc(131.4,31.4) 131.52,30.82 131.52,29.19 arc(131.61,28.97) 131.82,28.88 131.86,28.88 arc(132,28.91) 132.11,28.99 132.13,29.01 arc(132.2,29.11) 132.23,29.23 v1(132.23,29.38)
  BOTTOM w0.084: v1(94.77,45.46) 94.77,45.28 arc(94.75,45.17) 94.69,45.08 94.67,45.07 arc(94.58,45.01) 94.48,44.99 93.71,44.99 arc(93.66,45.01) 93.64,45.06 arc(93.62,45.11) 93.56,45.14 93.38,45.14 arc(93.32,45.11) 93.3,45.06 arc(93.28,45.01) 93.23,44.99 93.04,44.99 arc(92.99,45.01) 92.97,45.06 arc(92.95,45.11) 92.89,45.14 92.71,45.14 arc(92.65,45.11) 92.63,45.06 arc(92.61,45.01) 92.56,44.99 92.37,44.99 arc(92.32,45.01) 92.3,45.06 arc(92.27,45.11) 92.22,45.14 92.04,45.14 arc(91.98,45.11) 91.96,45.06 arc(91.94,45.01) 91.89,44.99 89.14,44.99 arc(88.5,44.86) 87.95,44.5 87.57,44.11 arc(87.24,43.89) 86.84,43.81 86.82,43.81 arc(86.42,43.89) 86.09,44.11 85.74,44.46 arc(85.53,44.6) 85.28,44.65 85.21,44.65 arc(85.07,44.71) 85,44.86 85,45.16 arc(84.6,45.57) 84.19,45.16 84.19,45.12 arc(84.05,44.79) 83.72,44.65 83.45,44.65 arc(83.29,44.71) 83.23,44.86 83.23,47.41 arc(83.02,47.92) 82.51,48.13 78.46,48.13 arc(78.31,48.19) 78.25,48.33 78.25,48.48 arc(78.28,48.53) 78.33,48.55 arc(78.39,48.58) 78.41,48.63 78.41,48.81 arc(78.39,48.87) 78.33,48.89 arc(78.28,48.91) 78.25,48.97 78.25,49.15 arc(78.28,49.2) 78.33,49.23 arc(78.39,49.25) 78.41,49.3 78.41,49.48 arc(78.39,49.54) 78.33,49.56 arc(78.28,49.58) 78.25,49.64 78.25,49.82 arc(78.28,49.87) 78.33,49.9 arc(78.39,49.92) 78.41,49.97 78.41,50.15 arc(78.39,50.21) 78.33,50.23 arc(78.28,50.25) 78.25,50.31 78.25,50.67 arc(78.29,50.75) 78.37,50.79 v1(78.52,50.79)
MIPI_DPHY_DSI_TX_D1P: length 91.1
  TOP w0.084: CN3.18 79.12,49.42 arc(79.11,49.48) 79.08,49.53 79.07,49.54 arc(79.03,49.59) 79.02,49.65 79.02,50.69 arc(78.98,50.91) 78.86,51.09 78.65,51.3 arc(78.55,51.44) 78.52,51.6 v1(78.52,51.79) ; v1(132.23,28.49) 132.35,28.62 arc(132.48,28.71) 132.63,28.74 132.73,28.74 arc(132.91,28.66) 132.98,28.49 132.98,26.98 arc(133.1,26.33) 133.47,25.79 134.2,25.06 arc(134.74,24.69) 135.38,24.57 136.21,24.57 arc(136.78,24.45) 137.26,24.13 138.7,22.69 arc(139.25,22.32) 139.89,22.2 142.45,22.2 arc(142.54,22.18) 142.62,22.13 142.63,22.12 arc(142.71,22.06) 142.8,22.05 J13.20
  ART03 w0.076: v1(132.23,28.49) 132.13,28.59 arc(132.03,28.66) 131.91,28.68 131.82,28.68 arc(131.46,28.83) 131.31,29.19 131.31,30.82 arc(131.21,31.33) 130.93,31.75 130.48,32.2 arc(130.05,32.49) 129.54,32.59 123.56,32.59 arc(122.98,32.7) 122.48,33.03 118.94,36.57 arc(118.72,36.91) 118.64,37.3 118.64,39.53 arc(118.54,40.04) 118.26,40.47 116.21,42.51 arc(116.06,42.61) 115.89,42.65 98.36,42.65 arc(97.78,42.76) 97.28,43.09 95.77,44.6 arc(95.57,44.74) 95.33,44.79 95.13,44.79 arc(94.99,44.76) 94.88,44.68 v1(94.77,44.57)
  BOTTOM w0.084: v1(94.77,44.57) 94.6,44.74 arc(94.54,44.78) 94.48,44.79 89.14,44.79 arc(88.57,44.68) 88.09,44.36 87.71,43.97 arc(87.31,43.71) 86.84,43.61 86.82,43.61 arc(86.35,43.71) 85.95,43.97 85.6,44.32 arc(85.46,44.42) 85.28,44.45 85.21,44.45 arc(84.93,44.57) 84.81,44.86 84.81,45.16 arc(84.6,45.37) 84.39,45.16 84.39,45.12 arc(84.19,44.65) 83.72,44.45 83.45,44.45 arc(83.15,44.57) 83.03,44.86 83.03,47.35 arc(82.86,47.76) 82.45,47.93 78.46,47.93 arc(78.17,48.05) 78.05,48.33 78.05,50.79 arc(78.08,50.94) 78.17,51.07 78.4,51.3 arc(78.49,51.43) 78.52,51.59 v1(78.52,51.79)
MIPI_DPHY_DSI_TX_D2N: length 90.6
  TOP w0.084: CN3.8 77.12,49.42 arc(77.13,49.48) 77.17,49.53 77.18,49.54 arc(77.21,49.59) 77.22,49.65 77.22,49.8 arc(77.19,49.99) 77.08,50.14 76.9,50.33 arc(76.81,50.46) 76.78,50.61 76.78,50.7 arc(76.76,50.76) 76.7,50.79 v1(76.52,50.79) ; v1(130.25,29.43) 130.2,29.39 130.2,29.26 arc(130.22,29.17) 130.27,29.08 130.29,29.07 arc(130.38,29.01) 130.49,28.98 130.75,28.98 arc(131.07,28.86) 131.19,28.54 131.19,27 arc(131.31,26.43) 131.63,25.95 133.7,23.88 arc(134.18,23.56) 134.75,23.44 136.42,23.44 arc(136.63,23.4) 136.82,23.28 138.61,21.48 arc(139,21.22) 139.46,21.13 140.73,21.13 arc(140.88,21.1) 141.01,21.02 141.08,20.95 arc(141.14,20.91) 141.21,20.89 142.45,20.89 arc(142.54,20.91) 142.62,20.96 142.63,20.98 arc(142.7,21.03) 142.8,21.05 J13.18
  ART03 w0.076: v1(130.25,29.43) 130.25,29.4 arc(130.13,29.11) 129.84,28.99 124.4,28.99 arc(123.89,29.09) 123.47,29.37 115.25,37.59 arc(114.96,38.02) 114.86,38.53 114.86,39.37 arc(114.41,40.45) 113.33,40.89 97.65,40.89 arc(97.15,40.99) 96.72,41.28 95.88,42.12 arc(95.63,42.29) 95.32,42.35 95.07,42.35 arc(94.95,42.37) 94.85,42.44 94.85,42.44 arc(94.79,42.53) 94.77,42.63 v1(94.77,42.82)
  BOTTOM w0.084: v1(76.52,50.79) 76.34,50.79 arc(76.24,50.75) 76.2,50.65 76.2,50.4 arc(76.22,50.34) 76.28,50.32 arc(76.33,50.3) 76.35,50.25 76.35,50.06 arc(76.33,50.01) 76.28,49.99 arc(76.22,49.96) 76.2,49.91 76.2,49.73 arc(76.22,49.67) 76.28,49.65 arc(76.33,49.63) 76.35,49.58 76.35,49.39 arc(76.33,49.34) 76.28,49.32 arc(76.22,49.29) 76.2,49.24 76.2,49.06 arc(76.22,49) 76.28,48.98 arc(76.33,48.96) 76.35,48.9 76.35,48.72 arc(76.33,48.67) 76.28,48.65 arc(76.22,48.62) 76.2,48.57 76.2,48.21 arc(76.35,47.48) 76.76,46.86 77.73,45.9 arc(77.89,45.65) 77.95,45.36 77.95,44 arc(78.06,43.44) 78.38,42.96 79.04,42.29 arc(79.52,41.97) 80.09,41.86 87.39,41.86 arc(87.92,41.96) 88.37,42.27 88.43,42.33 arc(88.94,42.67) 89.55,42.79 90.79,42.79 arc(91.04,42.74) 91.26,42.6 91.33,42.53 arc(91.48,42.43) 91.66,42.4 92,42.4 arc(92.04,42.41) 92.06,42.46 arc(92.08,42.5) 92.12,42.52 92.33,42.52 arc(92.38,42.5) 92.39,42.46 arc(92.41,42.41) 92.46,42.4 92.67,42.4 arc(92.71,42.41) 92.73,42.46 arc(92.75,42.5) 92.79,42.52 93,42.52 arc(93.05,42.5) 93.06,42.46 arc(93.08,42.41) 93.13,42.4 93.34,42.4 arc(93.38,42.41) 93.4,42.46 arc(93.42,42.5) 93.46,42.52 93.67,42.52 arc(93.72,42.5) 93.74,42.46 arc(93.75,42.41) 93.8,42.4 94.01,42.4 arc(94.05,42.41) 94.07,42.46 arc(94.09,42.5) 94.13,42.52 94.34,42.52 arc(94.39,42.5) 94.41,42.46 arc(94.42,42.41) 94.47,42.4 94.6,42.4 arc(94.68,42.41) 94.74,42.46 94.77,42.48 arc(94.84,42.65) v1(94.77,42.82)
